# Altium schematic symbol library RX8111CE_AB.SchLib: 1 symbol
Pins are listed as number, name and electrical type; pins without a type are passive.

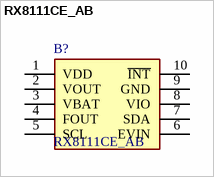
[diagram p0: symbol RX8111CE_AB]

## RX8111CE_AB
designator B?
Real Time Clock RX8111CE:AB REAL TIME CLOCK I2C-BUS 3.0V 11.5PPM BULK; Manufacturer_Name: Epson Timing; Manufacturer_Part_Number: RX8111CE AB; Geometry.Height: 1mm
footprint RX8111CEAB
pins: 1 VDD, 2 VOUT, 3 VBAT, 4 FOUT, 5 SCL, 6 EVIN, 7 SDA, 8 VIO, 9 GND, 10 ~{INT}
